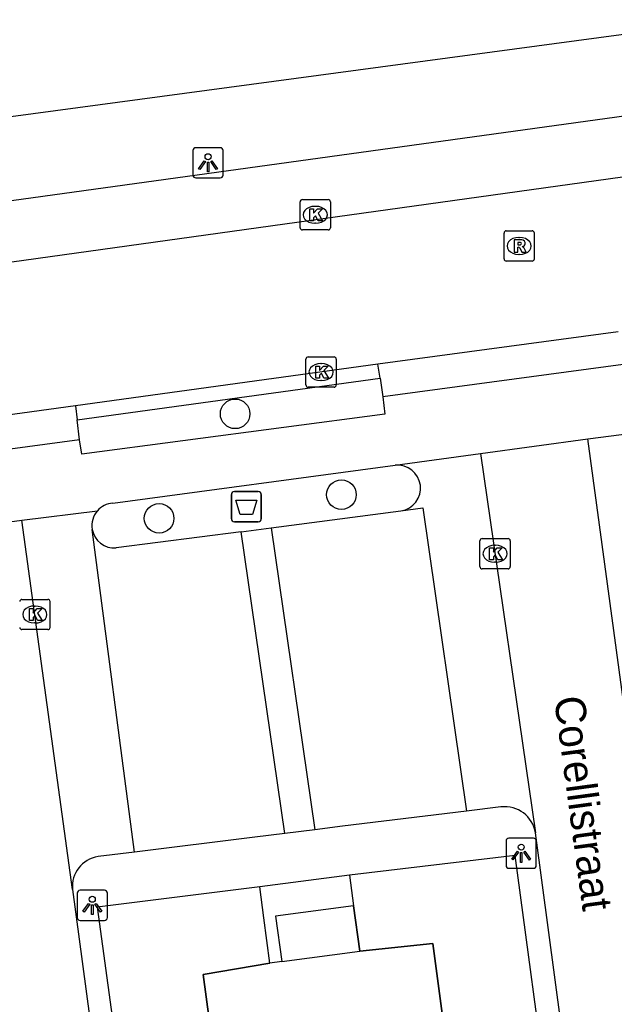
# Model space of a CAD drawing. Extents: x 159053 to 160041, y 380450 to 381422.
# Drawn here: x 159604.8 to 159624.44, y 380957.63 to 380990.15 of the extents above; entities that cross this region are included whole.
import ezdxf

# ---------------------------------------------------------------- set-up
doc = ezdxf.new("R2010")
doc.units = 0
for name, color, linetype in [('IMGEO_Afvalbak', 7, 'Continuous'), ('IMGEO_Boom', 7, 'Continuous'), ('IMGEO_Groenvoorziening', 7, 'Continuous'), ('IMGEO_Hek', 7, 'Continuous'), ('IMGEO_Kolk', 7, 'Continuous'), ('IMGEO_Lichtpunt', 7, 'Continuous'), ('IMGEO_Openbare_ruimte_label', 7, 'Continuous'), ('IMGEO_Parkeervlak_open', 7, 'Continuous'), ('IMGEO_Rijbaan_lokaal_open', 7, 'Continuous'), ('IMGEO_Rioolput', 7, 'Continuous'), ('IMGEO_Terreindeel_open', 7, 'Continuous'), ('IMGEO_Voetpad_op_trap', 7, 'Continuous'), ('IMGEO_Voetpad_open', 7, 'Continuous')]:
    doc.layers.add(name, color=color, linetype=linetype)

msp = doc.modelspace()

# ---------------------------------------------------------------- linework, layer by layer
at = {"layer": 'IMGEO_Afvalbak'}
for p, q in [((159611.79, 380973.668), (159611.79, 380974.468)), ((159611.79, 380974.468), (159611.79, 380973.668)), ((159611.89, 380974.568), (159612.68, 380974.568)), ((159612.68, 380974.568), (159611.89, 380974.568)), ((159612.78, 380974.468), (159612.78, 380973.668)), ((159612.78, 380973.668), (159612.78, 380974.468)), ((159612.68, 380973.568), (159611.89, 380973.568)), ((159611.89, 380973.568), (159612.68, 380973.568))]:
    msp.add_line(p, q, dxfattribs=at)
msp.add_lwpolyline([(159611.933, 380974.282), (159612.637, 380974.282), (159612.488, 380973.812), (159612.082, 380973.812), (159611.933, 380974.282)], dxfattribs=at)
for centre, start, end in [((159611.89, 380974.468), 90, 180), ((159611.89, 380974.468), 90, 180), ((159612.68, 380974.468), 0, 90), ((159612.68, 380974.468), 360, 90), ((159611.89, 380973.668), 180, 270), ((159611.89, 380973.668), 180, 270), ((159612.68, 380973.668), 270, 0), ((159612.68, 380973.668), 270, 0)]:
    msp.add_arc(centre, 0.1, start, end, dxfattribs=at)
at = {"layer": 'IMGEO_Boom'}
for centre in [(159611.916, 380977.133), (159615.425, 380974.463), (159609.406, 380973.681)]:
    msp.add_circle(centre, 0.489, dxfattribs=at)
at = {"layer": 'IMGEO_Groenvoorziening'}
for points in [[(159616.029, 380959.381), (159615.828, 380960.877), (159613.251, 380960.54), (159613.453, 380959.044)], [(159613.453, 380959.044), (159613.065, 380958.993), (159610.857, 380958.617), (159612.539, 380946.079), (159620.121, 380947.097), (159618.439, 380959.635), (159616.029, 380959.381)]]:
    msp.add_lwpolyline(points, dxfattribs=at)
at = {"layer": 'IMGEO_Hek'}
for points in [[(159615.691, 380961.898), (159615.828, 380960.877)], [(159612.863, 380960.489), (159612.726, 380961.51)], [(159615.828, 380960.877), (159616.029, 380959.381)], [(159613.065, 380958.993), (159612.863, 380960.489)], [(159616.029, 380959.381), (159618.439, 380959.635), (159620.121, 380947.097), (159612.539, 380946.079), (159610.857, 380958.617), (159613.065, 380958.993)]]:
    msp.add_lwpolyline(points, dxfattribs=at)
at = {"layer": 'IMGEO_Kolk'}
for p, q in [((159614.135, 380984.207), (159614.987, 380984.207)), ((159614.06, 380983.281), (159614.06, 380984.133)), ((159614.548, 380983.987), (159614.573, 380983.987)), ((159615.061, 380984.133), (159615.061, 380983.281)), ((159614.987, 380983.207), (159614.135, 380983.207)), ((159614.571, 380983.427), (159614.546, 380983.427)), ((159614.329, 380979.013), (159615.181, 380979.013)), ((159614.254, 380978.087), (159614.254, 380978.939)), ((159614.742, 380978.793), (159614.767, 380978.793)), ((159615.255, 380978.939), (159615.255, 380978.087)), ((159615.181, 380978.013), (159614.329, 380978.013)), ((159614.765, 380978.233), (159614.74, 380978.233)), ((159619.999, 380972.086), (159619.999, 380972.938)), ((159620.074, 380973.012), (159620.926, 380973.012)), ((159620.487, 380972.792), (159620.512, 380972.792)), ((159621, 380972.938), (159621, 380972.086)), ((159620.51, 380972.232), (159620.485, 380972.232)), ((159620.926, 380972.012), (159620.074, 380972.012)), ((159604.876, 380971.005), (159605.728, 380971.005)), ((159605.802, 380970.931), (159605.802, 380970.079)), ((159605.289, 380970.785), (159605.314, 380970.785)), ((159605.312, 380970.225), (159605.287, 380970.225)), ((159605.728, 380970.005), (159604.876, 380970.005))]:
    msp.add_line(p, q, dxfattribs=at)
for points in [[(159614.135, 380984.207), (159614.987, 380984.207)], [(159614.06, 380983.281), (159614.06, 380984.133)], [(159614.381, 380983.907), (159614.504, 380983.907), (159614.504, 380983.756), (159614.634, 380983.907), (159614.798, 380983.907), (159614.652, 380983.756), (159614.805, 380983.507), (159614.653, 380983.507), (159614.568, 380983.671), (159614.504, 380983.604), (159614.504, 380983.507), (159614.381, 380983.507), (159614.381, 380983.907)], [(159615.061, 380984.133), (159615.061, 380983.281)], [(159614.987, 380983.207), (159614.135, 380983.207)], [(159614.329, 380979.013), (159615.181, 380979.013)], [(159614.254, 380978.087), (159614.254, 380978.939)], [(159614.575, 380978.713), (159614.698, 380978.713), (159614.698, 380978.562), (159614.828, 380978.713), (159614.992, 380978.713), (159614.846, 380978.562), (159614.999, 380978.313), (159614.847, 380978.313), (159614.762, 380978.477), (159614.698, 380978.41), (159614.698, 380978.313), (159614.575, 380978.313), (159614.575, 380978.713)], [(159615.255, 380978.939), (159615.255, 380978.087)], [(159615.181, 380978.013), (159614.329, 380978.013)], [(159619.999, 380972.086), (159619.999, 380972.938)], [(159620.074, 380973.012), (159620.926, 380973.012)], [(159621, 380972.938), (159621, 380972.086)], [(159620.32, 380972.712), (159620.443, 380972.712), (159620.443, 380972.561), (159620.573, 380972.712), (159620.737, 380972.712), (159620.591, 380972.561), (159620.744, 380972.312), (159620.592, 380972.312), (159620.507, 380972.476), (159620.443, 380972.409), (159620.443, 380972.312), (159620.32, 380972.312), (159620.32, 380972.712)], [(159620.926, 380972.012), (159620.074, 380972.012)], [(159604.876, 380971.005), (159605.728, 380971.005)], [(159605.802, 380970.931), (159605.802, 380970.079)], [(159605.122, 380970.705), (159605.245, 380970.705), (159605.245, 380970.554), (159605.375, 380970.705), (159605.539, 380970.705), (159605.393, 380970.554), (159605.546, 380970.305), (159605.394, 380970.305), (159605.309, 380970.469), (159605.245, 380970.402), (159605.245, 380970.305), (159605.122, 380970.305), (159605.122, 380970.705)], [(159605.728, 380970.005), (159604.876, 380970.005)]]:
    msp.add_lwpolyline(points, dxfattribs=at)
for centre, start, end in [((159614.137, 380984.131), 91.552, 178.448), ((159614.137, 380984.131), 91.552, 178.448), ((159614.985, 380984.131), 1.552, 88.448), ((159614.985, 380984.131), 1.552, 88.448), ((159614.137, 380983.283), 181.552, 268.448), ((159614.137, 380983.283), 181.552, 268.448), ((159614.985, 380983.283), 271.552, 358.448), ((159614.985, 380983.283), 271.552, 358.448), ((159614.331, 380978.937), 91.552, 178.448), ((159614.331, 380978.937), 91.552, 178.448), ((159615.179, 380978.937), 1.552, 88.448), ((159615.179, 380978.937), 1.552, 88.448), ((159614.331, 380978.089), 181.552, 268.448), ((159614.331, 380978.089), 181.552, 268.448), ((159615.179, 380978.089), 271.552, 358.448), ((159615.179, 380978.089), 271.552, 358.448), ((159620.076, 380972.936), 91.552, 178.448), ((159620.076, 380972.936), 91.552, 178.448), ((159620.924, 380972.936), 1.552, 88.448), ((159620.924, 380972.936), 1.552, 88.448), ((159620.076, 380972.088), 181.552, 268.448), ((159620.076, 380972.088), 181.552, 268.448), ((159620.924, 380972.088), 271.552, 358.448), ((159620.924, 380972.088), 271.552, 358.448), ((159604.878, 380970.929), 91.552, 178.448), ((159604.878, 380970.929), 91.552, 178.448), ((159605.726, 380970.929), 1.552, 88.448), ((159605.726, 380970.929), 1.552, 88.448), ((159604.878, 380970.081), 181.552, 268.448), ((159604.878, 380970.081), 181.552, 268.448), ((159605.726, 380970.081), 271.552, 358.448), ((159605.726, 380970.081), 271.552, 358.448)]:
    msp.add_arc(centre, 0.0765, start, end, dxfattribs=at)
for centre, major_axis, ratio, start_param, end_param in [((159614.547, 380983.707), (-0.387, 0.002), 0.722429, 4.712389, 7.853982), ((159614.572, 380983.707), (-0.39, 0.002), 0.717154, 1.570796, 4.712389), ((159614.741, 380978.513), (-0.387, 0.002), 0.722429, 4.712389, 7.853982), ((159614.766, 380978.513), (-0.39, 0.002), 0.717154, 1.570796, 4.712389), ((159620.486, 380972.512), (-0.387, 0.002), 0.722429, 4.712389, 7.853982), ((159620.511, 380972.512), (-0.39, 0.002), 0.717154, 1.570796, 4.712389), ((159605.288, 380970.505), (-0.387, 0.002), 0.722429, 4.712389, 7.853982), ((159605.313, 380970.505), (-0.39, 0.002), 0.717154, 1.570796, 4.712389)]:
    msp.add_ellipse(centre, major_axis=major_axis, ratio=ratio, start_param=start_param, end_param=end_param, dxfattribs=at)
at = {"layer": 'IMGEO_Lichtpunt'}
for p, q in [((159610.522, 380985.828), (159610.522, 380985.021)), ((159610.522, 380985.828), (159610.522, 380985.021)), ((159611.424, 380985.923), (159610.616, 380985.923)), ((159611.424, 380985.923), (159610.616, 380985.923)), ((159611.518, 380985.021), (159611.518, 380985.828)), ((159611.518, 380985.021), (159611.518, 380985.828)), ((159610.616, 380984.927), (159611.424, 380984.927)), ((159610.616, 380984.927), (159611.424, 380984.927)), ((159620.862, 380963.023), (159620.862, 380962.216)), ((159620.862, 380963.023), (159620.862, 380962.216)), ((159621.764, 380963.118), (159620.956, 380963.118)), ((159621.764, 380963.118), (159620.956, 380963.118)), ((159621.858, 380962.216), (159621.858, 380963.023)), ((159621.858, 380962.216), (159621.858, 380963.023)), ((159620.956, 380962.122), (159621.764, 380962.122)), ((159620.956, 380962.122), (159621.764, 380962.122)), ((159607.602, 380961.395), (159606.794, 380961.395)), ((159607.602, 380961.395), (159606.794, 380961.395)), ((159606.7, 380961.3), (159606.7, 380960.493)), ((159606.7, 380961.3), (159606.7, 380960.493)), ((159607.696, 380960.493), (159607.696, 380961.3)), ((159607.696, 380960.493), (159607.696, 380961.3)), ((159606.794, 380960.399), (159607.602, 380960.399)), ((159606.794, 380960.399), (159607.602, 380960.399))]:
    msp.add_line(p, q, dxfattribs=at)
for points in [[(159610.896, 380985.492), (159610.935, 380985.464), (159610.747, 380985.202), (159610.709, 380985.229), (159610.896, 380985.492)], [(159611.108, 380985.464), (159611.146, 380985.491), (159611.333, 380985.229), (159611.294, 380985.201), (159611.108, 380985.464)], [(159610.998, 380985.444), (159611.045, 380985.444), (159611.045, 380985.122), (159610.998, 380985.122), (159610.998, 380985.444)], [(159621.236, 380962.687), (159621.275, 380962.659), (159621.087, 380962.397), (159621.049, 380962.424), (159621.236, 380962.687)], [(159621.448, 380962.659), (159621.486, 380962.686), (159621.673, 380962.424), (159621.634, 380962.396), (159621.448, 380962.659)], [(159621.338, 380962.639), (159621.385, 380962.639), (159621.385, 380962.317), (159621.338, 380962.317), (159621.338, 380962.639)], [(159607.074, 380960.964), (159607.113, 380960.936), (159606.925, 380960.674), (159606.887, 380960.701), (159607.074, 380960.964)], [(159607.176, 380960.916), (159607.223, 380960.916), (159607.223, 380960.594), (159607.176, 380960.594), (159607.176, 380960.916)], [(159607.286, 380960.936), (159607.324, 380960.963), (159607.511, 380960.701), (159607.472, 380960.673), (159607.286, 380960.936)]]:
    msp.add_lwpolyline(points, dxfattribs=at)
for centre in [(159611.021, 380985.626), (159621.361, 380962.821), (159607.199, 380961.098)]:
    msp.add_circle(centre, 0.0994, dxfattribs=at)
for centre, start, end in [((159610.616, 380985.828), 90, 180), ((159610.616, 380985.828), 90, 180), ((159611.424, 380985.828), 0, 90), ((159611.424, 380985.828), 0, 90), ((159610.616, 380985.021), 180, 270), ((159610.616, 380985.021), 180, 270), ((159611.424, 380985.021), 270, 0), ((159611.424, 380985.021), 270, 360), ((159620.956, 380963.023), 90, 180), ((159620.956, 380963.023), 90, 180), ((159621.764, 380963.023), 0, 90), ((159621.764, 380963.023), 0, 90), ((159620.956, 380962.216), 180, 270), ((159620.956, 380962.216), 180, 270), ((159621.764, 380962.216), 270, 0), ((159621.764, 380962.216), 270, 360), ((159606.794, 380961.3), 90, 180), ((159606.794, 380961.3), 90, 180), ((159607.602, 380961.3), 0, 90), ((159607.602, 380961.3), 0, 90), ((159606.794, 380960.493), 180, 270), ((159606.794, 380960.493), 180, 270), ((159607.602, 380960.493), 270, 0), ((159607.602, 380960.493), 270, 360)]:
    msp.add_arc(centre, 0.0946, start, end, dxfattribs=at)
at = {"layer": 'IMGEO_Parkeervlak_open'}
for points in [[(159617.39, 380973.928), (159618.112, 380974.023), (159619.556, 380964.011)], [(159608.59, 380962.656), (159607.196, 380973.318)]]:
    msp.add_lwpolyline(points, dxfattribs=at)
at = {"layer": 'IMGEO_Rijbaan_lokaal_open'}
for points in [[(159592.902, 380980.536), (159630.712, 380985.796)], [(159624.562, 380979.841), (159616.632, 380978.772)], [(159616.632, 380978.772), (159606.648, 380977.395)], [(159606.648, 380977.395), (159599.594, 380976.425)], [(159620.023, 380975.823), (159623.567, 380976.306)], [(159629.685, 380931.175), (159623.567, 380976.306)], [(159620.023, 380975.823), (159621.831, 380963.292)], [(159601.418, 380973.158), (159604.872, 380973.622)], [(159606.546, 380961.427), (159604.872, 380973.622)], [(159624.158, 380945.926), (159621.831, 380963.292)], [(159606.546, 380961.427), (159608.889, 380943.948)]]:
    msp.add_lwpolyline(points, dxfattribs=at)
at = {"layer": 'IMGEO_Rioolput'}
for p, q in [((159620.869, 380983.178), (159621.721, 380983.178)), ((159620.794, 380982.252), (159620.794, 380983.104)), ((159621.282, 380982.958), (159621.307, 380982.958)), ((159621.795, 380983.104), (159621.795, 380982.252)), ((159621.305, 380982.398), (159621.28, 380982.398)), ((159621.721, 380982.178), (159620.869, 380982.178))]:
    msp.add_line(p, q, dxfattribs=at)
for points in [[(159620.869, 380983.178), (159621.721, 380983.178)], [(159620.794, 380982.252), (159620.794, 380983.104)], [(159621.383, 380982.876), (159621.131, 380982.878), (159621.131, 380982.478)], [(159621.795, 380983.104), (159621.795, 380982.252)], [(159621.131, 380982.478), (159621.255, 380982.478), (159621.255, 380982.64), (159621.266, 380982.64)], [(159621.309, 380982.797), (159621.255, 380982.797), (159621.255, 380982.716)], [(159621.255, 380982.716), (159621.307, 380982.716)], [(159621.313, 380982.611), (159621.384, 380982.478), (159621.524, 380982.478), (159621.459, 380982.604)], [(159621.721, 380982.178), (159620.869, 380982.178)]]:
    msp.add_lwpolyline(points, dxfattribs=at)
for centre, radius, start, end in [((159620.871, 380983.102), 0.0765, 91.552, 178.448), ((159620.871, 380983.102), 0.0765, 91.552, 178.448), ((159621.719, 380983.102), 0.0765, 1.552, 88.448), ((159621.719, 380983.102), 0.0765, 1.552, 88.448), ((159621.382, 380982.766), 0.109, 350.3612, 89.416), ((159621.265, 380982.587), 0.0533, 26.0293, 88.6989), ((159621.291, 380982.905), 0.19, 274.7715, 282.9687), ((159621.315, 380982.701), 0.0964, 77.0061, 93.1865), ((159621.329, 380982.758), 0.0378, 276.6634, 79.6772), ((159621.38, 380982.766), 0.112, 277.5842, 350.9817), ((159621.364, 380982.551), 0.108, 29.5134, 73.7905), ((159620.871, 380982.254), 0.0765, 181.552, 268.448), ((159620.871, 380982.254), 0.0765, 181.552, 268.448), ((159621.719, 380982.254), 0.0765, 271.552, 358.448), ((159621.719, 380982.254), 0.0765, 271.552, 358.448)]:
    msp.add_arc(centre, radius, start, end, dxfattribs=at)
for centre, major_axis, ratio, start_param, end_param in [((159621.281, 380982.678), (-0.387, 0.002), 0.722429, 4.712389, 7.853982), ((159621.306, 380982.678), (-0.39, 0.002), 0.717154, 1.570796, 4.712389)]:
    msp.add_ellipse(centre, major_axis=major_axis, ratio=ratio, start_param=start_param, end_param=end_param, dxfattribs=at)
at = {"layer": 'IMGEO_Terreindeel_open'}
msp.add_lwpolyline([(159613.453, 380959.044), (159616.029, 380959.381)], dxfattribs=at)
at = {"layer": 'IMGEO_Voetpad_op_trap'}
for points in [[(159632.613, 380990.715), (159590.084, 380985.004)], [(159594.727, 380982.821), (159628.576, 380987.503)], [(159624.733, 380978.767), (159616.793, 380977.691)], [(159616.701, 380978.31), (159616.793, 380977.691)], [(159616.793, 380977.691), (159616.854, 380977.123), (159606.851, 380975.797), (159606.771, 380976.277)], [(159606.771, 380976.277), (159606.699, 380976.931)], [(159606.771, 380976.277), (159599.734, 380975.322)], [(159617.199, 380975.434), (159620.023, 380975.823)], [(159604.872, 380973.622), (159607.369, 380973.933)]]:
    msp.add_lwpolyline(points, dxfattribs=at)
at = {"layer": 'IMGEO_Voetpad_open'}
for points in [[(159616.701, 380978.31), (159616.632, 380978.772)], [(159606.699, 380976.931), (159616.701, 380978.31)], [(159606.648, 380977.395), (159606.699, 380976.931)], [(159623.567, 380976.306), (159625.356, 380976.539)], [(159607.873, 380974.185), (159617.199, 380975.434)], [(159613.104, 380973.37), (159617.39, 380973.928)], [(159612.112, 380973.241), (159607.989, 380972.704)], [(159612.112, 380973.241), (159613.104, 380973.37)], [(159613.551, 380963.272), (159612.112, 380973.241)], [(159613.104, 380973.37), (159614.544, 380963.398)], [(159619.556, 380964.011), (159615.463, 380963.514), (159614.544, 380963.398)], [(159620.694, 380964.149), (159619.556, 380964.011)], [(159614.544, 380963.398), (159613.551, 380963.272)], [(159613.551, 380963.272), (159612.562, 380963.147), (159608.59, 380962.656)], [(159621.161, 380962.546), (159615.691, 380961.898), (159612.726, 380961.51), (159607.364, 380960.833), (159609.687, 380943.846), (159623.433, 380945.68), (159621.161, 380962.546)], [(159608.59, 380962.656), (159607.388, 380962.507)]]:
    msp.add_lwpolyline(points, dxfattribs=at)
for centre, radius, start, end in [((159617.278, 380974.679), 0.759, 278.5013, 95.9547), ((159607.926, 380973.449), 0.738, 94.1201, 139.01), ((159607.928, 380973.444), 0.743, 138.8217, 189.7556), ((159607.928, 380973.444), 0.742, 189.7663, 274.7343), ((159620.818, 380963.13), 1.026, 9.0662, 96.9203), ((159607.537, 380961.523), 0.996, 98.6055, 185.5125)]:
    msp.add_arc(centre, radius, start, end, dxfattribs=at)

# ---------------------------------------------------------------- texts
at = {"layer": 'IMGEO_Openbare_ruimte_label'}
msp.add_text('Corellistraat', height=1, rotation=277.7007, dxfattribs=at).set_placement((159622.443, 380967.747))

doc.saveas('drawing.dxf')
